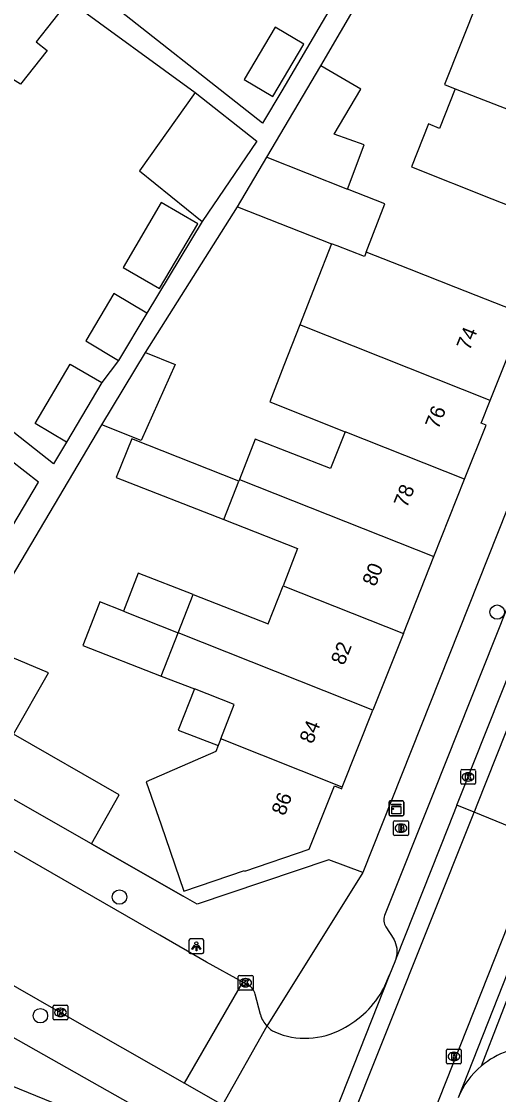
# Model space of a CAD drawing. Extents: x 160026 to 161302, y 384757 to 385701.
# Drawn here: x 160426.3 to 160458.6, y 385061.5 to 385134.3 of the extents above; entities that cross this region are included whole.
import ezdxf

# ---------------------------------------------------------------- set-up
doc = ezdxf.new("R2010")
doc.units = 0
for name, color, linetype in [('IMGEO_Boom', 7, 'Continuous'), ('IMGEO_Brandkraan', 7, 'Continuous'), ('IMGEO_Kast', 7, 'Continuous'), ('IMGEO_Kolk', 7, 'Continuous'), ('IMGEO_Lichtpunt', 7, 'Continuous'), ('IMGEO_Muur', 7, 'Continuous'), ('IMGEO_Pand', 7, 'Continuous'), ('IMGEO_Pand_nummerreeks', 7, 'Continuous'), ('IMGEO_Rijbaan_lokaal_gesloten', 7, 'Continuous'), ('IMGEO_Rijbaan_lokaal_open', 7, 'Continuous'), ('IMGEO_Rioolput', 7, 'Continuous'), ('IMGEO_Voetpad_open', 7, 'Continuous')]:
    doc.layers.add(name, color=color, linetype=linetype)

msp = doc.modelspace()

# ---------------------------------------------------------------- linework, layer by layer
at = {"layer": 'IMGEO_Boom'}
for centre in [(160458.507, 385094.238), (160432.899, 385074.913), (160427.536, 385066.863)]:
    msp.add_circle(centre, 0.489, dxfattribs=at)
at = {"layer": 'IMGEO_Brandkraan'}
for p, q in [((160451.56, 385080.088), (160452.412, 385080.088)), ((160451.485, 385079.162), (160451.485, 385080.014)), ((160451.973, 385079.868), (160451.998, 385079.868)), ((160452.486, 385080.014), (160452.486, 385079.162)), ((160452.412, 385079.088), (160451.56, 385079.088)), ((160451.996, 385079.308), (160451.971, 385079.308))]:
    msp.add_line(p, q, dxfattribs=at)
for points in [[(160451.56, 385080.088), (160452.412, 385080.088)], [(160451.485, 385079.162), (160451.485, 385080.014)], [(160451.833, 385079.788), (160451.833, 385079.388), (160452.046, 385079.388)], [(160452.064, 385079.788), (160451.833, 385079.788)], [(160452.012, 385079.707), (160451.958, 385079.707), (160451.958, 385079.631)], [(160451.958, 385079.631), (160452.011, 385079.631)], [(160452.02, 385079.555), (160451.958, 385079.555), (160451.958, 385079.474)], [(160451.958, 385079.474), (160452.02, 385079.474)], [(160452.486, 385080.014), (160452.486, 385079.162)], [(160452.412, 385079.088), (160451.56, 385079.088)]]:
    msp.add_lwpolyline(points, dxfattribs=at)
for centre, radius, start, end in [((160451.562, 385080.012), 0.0765, 91.55205, 178.44795), ((160451.562, 385080.012), 0.0765, 91.55205, 178.44795), ((160452.41, 385080.012), 0.0765, 1.55205, 88.44795), ((160452.41, 385080.012), 0.0765, 1.55205, 88.44795), ((160452.013, 385079.669), 0.0379, 267.82845, 90.93552), ((160452.021, 385079.514), 0.0404, 269.87594, 90.50774), ((160452.052, 385079.639), 0.251, 268.66757, 293.53466), ((160452.068, 385079.643), 0.145, 59.4692, 91.53667), ((160452.093, 385079.69), 0.0922, 285.51372, 58.15012), ((160452.098, 385079.498), 0.105, 301.31148, 78.98903), ((160451.562, 385079.164), 0.0765, 181.55205, 268.44795), ((160451.562, 385079.164), 0.0765, 181.55205, 268.44795), ((160452.41, 385079.164), 0.0765, 271.55205, 358.44795), ((160452.41, 385079.164), 0.0765, 271.55205, 358.44795)]:
    msp.add_arc(centre, radius, start, end, dxfattribs=at)
for centre, major_axis, ratio, start_param, end_param in [((160451.972, 385079.588), (-0.387, 0.002), 0.722429, 4.712389, 7.853982), ((160451.997, 385079.588), (-0.39, 0.002), 0.717154, 1.570796, 4.712389)]:
    msp.add_ellipse(centre, major_axis=major_axis, ratio=ratio, start_param=start_param, end_param=end_param, dxfattribs=at)
at = {"layer": 'IMGEO_Kast'}
for p, q in [((160451.176, 385080.508), (160451.176, 385081.349)), ((160451.176, 385081.349), (160451.176, 385080.508)), ((160451.251, 385081.433), (160452.092, 385081.433)), ((160452.092, 385081.433), (160451.251, 385081.433)), ((160452.176, 385081.358), (160452.176, 385080.517)), ((160452.176, 385080.517), (160452.176, 385081.358)), ((160452.101, 385080.433), (160451.26, 385080.433)), ((160451.26, 385080.433), (160452.101, 385080.433))]:
    msp.add_line(p, q, dxfattribs=at)
for points in [[(160451.371, 385081.223), (160451.971, 385081.223), (160451.971, 385081.138), (160451.371, 385081.138), (160451.371, 385081.223)], [(160451.371, 385081.048), (160451.971, 385081.048), (160451.971, 385080.559), (160451.371, 385080.559), (160451.371, 385081.048)]]:
    msp.add_lwpolyline(points, dxfattribs=at)
msp.add_circle((160451.455, 385080.897), 0.0377, dxfattribs=at)
for centre, start, end in [((160451.254, 385081.355), 92.4484, 184.28452), ((160451.254, 385081.355), 92.4484, 184.28452), ((160452.098, 385081.355), 2.4484, 94.28452), ((160452.098, 385081.355), 2.4484, 94.28452), ((160451.254, 385080.511), 182.4484, 274.28452), ((160451.254, 385080.511), 182.4484, 274.28452), ((160452.098, 385080.511), 272.4484, 4.28452), ((160452.098, 385080.511), 272.4484, 4.28452)]:
    msp.add_arc(centre, 0.0779, start, end, dxfattribs=at)
at = {"layer": 'IMGEO_Kolk'}
for p, q in [((160456.034, 385082.633), (160456.034, 385083.485)), ((160456.109, 385083.559), (160456.961, 385083.559)), ((160456.522, 385083.339), (160456.547, 385083.339)), ((160457.035, 385083.485), (160457.035, 385082.633)), ((160456.961, 385082.559), (160456.109, 385082.559)), ((160456.545, 385082.779), (160456.52, 385082.779)), ((160440.953, 385068.676), (160440.953, 385069.528)), ((160441.028, 385069.602), (160441.88, 385069.602)), ((160441.441, 385069.382), (160441.466, 385069.382)), ((160441.954, 385069.528), (160441.954, 385068.676)), ((160441.88, 385068.602), (160441.028, 385068.602)), ((160441.464, 385068.822), (160441.439, 385068.822)), ((160428.399, 385066.665), (160428.399, 385067.517)), ((160428.474, 385067.591), (160429.326, 385067.591)), ((160428.887, 385067.371), (160428.912, 385067.371)), ((160429.4, 385067.517), (160429.4, 385066.665)), ((160429.326, 385066.591), (160428.474, 385066.591)), ((160428.91, 385066.811), (160428.885, 385066.811))]:
    msp.add_line(p, q, dxfattribs=at)
for points in [[(160456.034, 385082.633), (160456.034, 385083.485)], [(160456.109, 385083.559), (160456.961, 385083.559)], [(160456.355, 385083.259), (160456.478, 385083.259), (160456.478, 385083.108), (160456.608, 385083.259), (160456.772, 385083.259), (160456.626, 385083.108), (160456.779, 385082.859), (160456.627, 385082.859), (160456.542, 385083.023), (160456.478, 385082.956), (160456.478, 385082.859), (160456.355, 385082.859), (160456.355, 385083.259)], [(160457.035, 385083.485), (160457.035, 385082.633)], [(160456.961, 385082.559), (160456.109, 385082.559)], [(160440.953, 385068.676), (160440.953, 385069.528)], [(160441.028, 385069.602), (160441.88, 385069.602)], [(160441.274, 385069.302), (160441.397, 385069.302), (160441.397, 385069.151), (160441.527, 385069.302), (160441.691, 385069.302), (160441.545, 385069.151), (160441.698, 385068.902), (160441.546, 385068.902), (160441.461, 385069.066), (160441.397, 385068.999), (160441.397, 385068.902), (160441.274, 385068.902), (160441.274, 385069.302)], [(160441.954, 385069.528), (160441.954, 385068.676)], [(160441.88, 385068.602), (160441.028, 385068.602)], [(160428.399, 385066.665), (160428.399, 385067.517)], [(160428.474, 385067.591), (160429.326, 385067.591)], [(160428.72, 385067.291), (160428.843, 385067.291), (160428.843, 385067.14), (160428.973, 385067.291), (160429.137, 385067.291), (160428.991, 385067.14), (160429.144, 385066.891), (160428.992, 385066.891), (160428.907, 385067.055), (160428.843, 385066.988), (160428.843, 385066.891), (160428.72, 385066.891), (160428.72, 385067.291)], [(160429.4, 385067.517), (160429.4, 385066.665)], [(160429.326, 385066.591), (160428.474, 385066.591)]]:
    msp.add_lwpolyline(points, dxfattribs=at)
for centre, start, end in [((160456.111, 385083.483), 91.55205, 178.44795), ((160456.111, 385083.483), 91.55205, 178.44795), ((160456.959, 385083.483), 1.55205, 88.44795), ((160456.959, 385083.483), 1.55205, 88.44795), ((160456.111, 385082.635), 181.55205, 268.44795), ((160456.111, 385082.635), 181.55205, 268.44795), ((160456.959, 385082.635), 271.55205, 358.44795), ((160456.959, 385082.635), 271.55205, 358.44795), ((160441.03, 385069.526), 91.55205, 178.44795), ((160441.03, 385069.526), 91.55205, 178.44795), ((160441.878, 385069.526), 1.55205, 88.44795), ((160441.878, 385069.526), 1.55205, 88.44795), ((160441.03, 385068.678), 181.55205, 268.44795), ((160441.03, 385068.678), 181.55205, 268.44795), ((160441.878, 385068.678), 271.55205, 358.44795), ((160441.878, 385068.678), 271.55205, 358.44795), ((160428.476, 385067.515), 91.55205, 178.44795), ((160428.476, 385067.515), 91.55205, 178.44795), ((160429.324, 385067.515), 1.55205, 88.44795), ((160429.324, 385067.515), 1.55205, 88.44795), ((160428.476, 385066.667), 181.55205, 268.44795), ((160428.476, 385066.667), 181.55205, 268.44795), ((160429.324, 385066.667), 271.55205, 358.44795), ((160429.324, 385066.667), 271.55205, 358.44795)]:
    msp.add_arc(centre, 0.0765, start, end, dxfattribs=at)
for centre, major_axis, ratio, start_param, end_param in [((160456.521, 385083.059), (-0.387, 0.002), 0.722429, 4.712389, 7.853982), ((160456.546, 385083.059), (-0.39, 0.002), 0.717154, 1.570796, 4.712389), ((160441.44, 385069.102), (-0.387, 0.002), 0.722429, 4.712389, 7.853982), ((160441.465, 385069.102), (-0.39, 0.002), 0.717154, 1.570796, 4.712389), ((160428.886, 385067.091), (-0.387, 0.002), 0.722429, 4.712389, 7.853982), ((160428.911, 385067.091), (-0.39, 0.002), 0.717154, 1.570796, 4.712389)]:
    msp.add_ellipse(centre, major_axis=major_axis, ratio=ratio, start_param=start_param, end_param=end_param, dxfattribs=at)
at = {"layer": 'IMGEO_Lichtpunt'}
for p, q in [((160437.613, 385071.976), (160437.613, 385071.169)), ((160437.613, 385071.976), (160437.613, 385071.169)), ((160438.515, 385072.071), (160437.707, 385072.071)), ((160438.515, 385072.071), (160437.707, 385072.071)), ((160438.609, 385071.169), (160438.609, 385071.976)), ((160438.609, 385071.169), (160438.609, 385071.976)), ((160437.707, 385071.075), (160438.515, 385071.075)), ((160437.707, 385071.075), (160438.515, 385071.075))]:
    msp.add_line(p, q, dxfattribs=at)
for points in [[(160437.987, 385071.64), (160438.026, 385071.612), (160437.838, 385071.35), (160437.8, 385071.377), (160437.987, 385071.64)], [(160438.089, 385071.592), (160438.136, 385071.592), (160438.136, 385071.27), (160438.089, 385071.27), (160438.089, 385071.592)], [(160438.199, 385071.612), (160438.237, 385071.639), (160438.424, 385071.377), (160438.385, 385071.349), (160438.199, 385071.612)]]:
    msp.add_lwpolyline(points, dxfattribs=at)
msp.add_circle((160438.112, 385071.774), 0.0994, dxfattribs=at)
for centre, start, end in [((160437.707, 385071.976), 90, 180), ((160437.707, 385071.976), 90, 180), ((160438.515, 385071.976), 0, 90), ((160438.515, 385071.976), 0, 90), ((160437.707, 385071.169), 180, 270), ((160437.707, 385071.169), 180, 270), ((160438.515, 385071.169), 270, 0), ((160438.515, 385071.169), 270, 360)]:
    msp.add_arc(centre, 0.0946, start, end, dxfattribs=at)
at = {"layer": 'IMGEO_Muur'}
msp.add_lwpolyline([(160430.992, 385078.531), (160437.229, 385074.968)], dxfattribs=at)
at = {"layer": 'IMGEO_Pand'}
for points in [[(160429.474, 385135.723), (160427.258, 385132.915), (160427.989, 385132.338), (160426.18, 385130.045), (160425.462, 385130.507)], [(160465.033, 385126.08), (160467.261, 385131.724), (160462.611, 385133.56), (160457.19, 385135.7), (160454.945, 385130.013), (160455.658, 385129.731)], [(160441.357, 385130.364), (160443.306, 385129.209), (160445.408, 385132.754), (160443.459, 385133.91), (160441.357, 385130.364)], [(160442.894, 385125.095), (160446.548, 385131.291)], [(160448.359, 385122.933), (160449.491, 385125.921), (160447.465, 385126.661), (160449.254, 385129.695), (160446.548, 385131.291)], [(160455.658, 385129.731), (160454.597, 385127.046), (160453.842, 385127.344), (160452.692, 385124.43), (160458.155, 385122.273), (160462.805, 385120.437), (160465.033, 385126.08)], [(160455.658, 385129.731), (160465.033, 385126.08)], [(160438.025, 385129.48), (160434.248, 385124.172), (160438.496, 385120.74)], [(160438.025, 385129.48), (160442.211, 385126.171), (160438.496, 385120.74)], [(160440.904, 385121.721), (160442.894, 385125.095)], [(160442.894, 385125.095), (160448.359, 385122.933)], [(160449.623, 385118.659), (160450.901, 385121.927), (160448.359, 385122.933)], [(160435.734, 385122.018), (160433.14, 385117.609), (160435.617, 385116.185), (160438.211, 385120.575), (160435.734, 385122.018)], [(160440.904, 385121.721), (160447.284, 385119.225)], [(160447.284, 385119.225), (160446.219, 385116.502), (160445.128, 385113.713)], [(160449.623, 385118.659), (160449.504, 385118.356), (160447.661, 385119.077), (160447.284, 385119.225)], [(160458.029, 385108.592), (160460.354, 385114.427), (160455.703, 385116.262), (160452.563, 385117.5), (160449.623, 385118.659)], [(160434.745, 385114.524), (160432.524, 385115.84), (160430.619, 385112.626), (160432.84, 385111.309)], [(160434.745, 385114.524), (160432.84, 385111.309)], [(160445.128, 385113.713), (160444.054, 385110.967), (160443.087, 385108.495), (160448.195, 385106.467)], [(160458.029, 385108.592), (160445.128, 385113.713)], [(160431.712, 385106.94), (160434.664, 385111.839)], [(160434.664, 385111.839), (160436.672, 385111.042), (160434.369, 385105.885), (160431.712, 385106.94)], [(160429.309, 385105.761), (160427.177, 385107.022), (160429.566, 385111.062), (160431.699, 385109.8)], [(160431.699, 385109.8), (160429.309, 385105.761)], [(160456.303, 385103.248), (160457.758, 385106.913), (160457.417, 385107.056), (160458.029, 385108.592)], [(160448.195, 385106.467), (160447.218, 385103.97), (160442.104, 385105.97), (160441.036, 385103.239)], [(160456.303, 385103.248), (160448.195, 385106.467)], [(160440.988, 385103.117), (160433.731, 385105.998), (160432.683, 385103.358), (160439.969, 385100.509)], [(160439.969, 385100.509), (160440.988, 385103.117)], [(160441.036, 385103.239), (160440.988, 385103.117)], [(160441.036, 385103.239), (160454.22, 385098.005)], [(160454.22, 385098.005), (160456.303, 385103.248)], [(160439.969, 385100.509), (160444.976, 385098.551), (160443.99, 385096.031)], [(160452.15, 385092.792), (160454.22, 385098.005)], [(160437.892, 385095.427), (160434.17, 385096.882), (160433.162, 385094.305)], [(160436.877, 385092.83), (160437.892, 385095.427)], [(160437.892, 385095.427), (160442.976, 385093.439), (160443.99, 385096.031)], [(160443.99, 385096.031), (160452.15, 385092.792)], [(160433.162, 385094.305), (160431.565, 385094.939), (160431.492, 385094.753), (160431.293, 385094.245), (160430.41, 385091.985), (160435.733, 385089.904)], [(160433.162, 385094.305), (160436.877, 385092.83)], [(160435.733, 385089.904), (160436.877, 385092.83)], [(160450.083, 385087.587), (160436.877, 385092.83)], [(160452.15, 385092.792), (160450.083, 385087.587)], [(160430.992, 385078.531), (160432.889, 385081.856), (160425.703, 385085.956), (160428.077, 385090.118), (160424.153, 385091.772)], [(160435.733, 385089.904), (160437.979, 385089.026)], [(160437.979, 385089.026), (160436.889, 385086.238), (160439.587, 385085.183)], [(160439.765, 385085.638), (160440.677, 385087.971), (160437.979, 385089.026)], [(160448.009, 385082.365), (160450.083, 385087.587)], [(160439.587, 385085.183), (160439.433, 385084.79), (160434.711, 385082.723), (160435.731, 385079.821), (160437.258, 385075.314), (160441.379, 385076.721), (160441.399, 385076.66), (160445.764, 385078.151), (160447.468, 385082.458), (160447.967, 385082.258), (160448.009, 385082.365)], [(160439.765, 385085.638), (160439.587, 385085.183)], [(160448.009, 385082.365), (160439.765, 385085.638)], [(160430.992, 385078.531), (160420.134, 385084.726)], [(160416.228, 385058.883), (160418.844, 385057.768), (160418.33, 385056.562), (160421.77, 385055.094), (160424.883, 385062.397), (160437.345, 385057.328), (160437.192, 385056.925), (160437.809, 385056.671), (160436.374, 385053.189), (160435.815, 385053.42), (160433.49, 385047.781)]]:
    msp.add_lwpolyline(points, dxfattribs=at)
at = {"layer": 'IMGEO_Rijbaan_lokaal_gesloten'}
for points in [[(160441.257, 385069.142), (160438.8, 385070.504), (160435.644, 385072.318), (160423.083, 385079.537)], [(160408.745, 385078.592), (160410.666, 385077.515), (160413.918, 385075.639), (160418.139, 385073.218), (160424.416, 385069.645), (160428.901, 385067.092), (160437.316, 385062.291)], [(160437.316, 385062.291), (160441.257, 385069.142)]]:
    msp.add_lwpolyline(points, dxfattribs=at)
at = {"layer": 'IMGEO_Rijbaan_lokaal_open'}
for points in [[(160455.778, 385081.134), (160455.964, 385081.607), (160471.018, 385119.416), (160484.621, 385153.583)], [(160485.703, 385153.152), (160472.155, 385118.996), (160457.14, 385081.141), (160456.95, 385080.661)], [(160455.778, 385081.134), (160455.177, 385079.664), (160451.665, 385070.767)], [(160456.95, 385080.661), (160455.778, 385081.134)], [(160444.248, 385048.841), (160445.179, 385051.173), (160456.884, 385080.495), (160456.95, 385080.661)], [(160461.545, 385078.805), (160456.95, 385080.661)], [(160461.545, 385078.805), (160461.163, 385077.845), (160449.849, 385049.309), (160448.949, 385047.038)], [(160462.221, 385077.395), (160455.854, 385061.298)], [(160457.441, 385063.46), (160459.941, 385069.896), (160462.004, 385075.033)], [(160451.665, 385070.767), (160451.564, 385070.512), (160451.217, 385069.636)], [(160451.217, 385069.636), (160444.275, 385052.096)], [(160450.82, 385068.727), (160451.217, 385069.636)], [(160441.637, 385068.931), (160441.441, 385069.04), (160441.257, 385069.142)], [(160442.461, 385066.94), (160442.105, 385068.325)], [(160442.902, 385066.151), (160439.877, 385060.829)], [(160437.316, 385062.291), (160439.877, 385060.829)]]:
    msp.add_lwpolyline(points, dxfattribs=at)
for centre, radius, start, end in [((160441.142, 385068.065), 0.997, 15.10373, 60.25245), ((160445.025, 385071.836), 6.576, 297.01428, 331.78995), ((160444.231, 385067.412), 1.832, 194.91909, 223.48565), ((160444.248, 385067.427), 1.854, 223.47168, 243.87053), ((160445.501, 385070.576), 5.24, 246.73836, 298.63582), ((160461.012, 385059.187), 5.568, 108.84467, 129.88312), ((160461.036, 385059.158), 5.607, 129.88196, 157.55753)]:
    msp.add_arc(centre, radius, start, end, dxfattribs=at)
at = {"layer": 'IMGEO_Rioolput'}
for p, q in [((160455.077, 385063.678), (160455.077, 385064.53)), ((160455.152, 385064.604), (160456.004, 385064.604)), ((160455.565, 385064.384), (160455.59, 385064.384)), ((160456.078, 385064.53), (160456.078, 385063.678)), ((160456.004, 385063.604), (160455.152, 385063.604)), ((160455.588, 385063.824), (160455.563, 385063.824))]:
    msp.add_line(p, q, dxfattribs=at)
for points in [[(160455.077, 385063.678), (160455.077, 385064.53)], [(160455.152, 385064.604), (160456.004, 385064.604)], [(160455.666, 385064.302), (160455.414, 385064.304), (160455.414, 385063.904)], [(160455.414, 385063.904), (160455.538, 385063.904), (160455.538, 385064.066), (160455.549, 385064.066)], [(160455.592, 385064.223), (160455.538, 385064.223), (160455.538, 385064.142)], [(160455.538, 385064.142), (160455.59, 385064.142)], [(160456.078, 385064.53), (160456.078, 385063.678)], [(160456.004, 385063.604), (160455.152, 385063.604)], [(160455.596, 385064.037), (160455.667, 385063.904), (160455.807, 385063.904), (160455.742, 385064.03)]]:
    msp.add_lwpolyline(points, dxfattribs=at)
for centre, radius, start, end in [((160455.154, 385064.528), 0.0765, 91.55205, 178.44795), ((160455.154, 385064.528), 0.0765, 91.55205, 178.44795), ((160455.548, 385064.013), 0.0533, 26.02933, 88.69889), ((160455.574, 385064.331), 0.19, 274.7715, 282.96867), ((160455.598, 385064.127), 0.0964, 77.00612, 93.18647), ((160455.612, 385064.184), 0.0378, 276.66336, 79.67722), ((160455.665, 385064.192), 0.109, 350.36119, 89.41601), ((160455.663, 385064.192), 0.112, 277.58423, 350.98172), ((160455.647, 385063.977), 0.108, 29.51342, 73.79051), ((160456.002, 385064.528), 0.0765, 1.55205, 88.44795), ((160456.002, 385064.528), 0.0765, 1.55205, 88.44795), ((160455.154, 385063.68), 0.0765, 181.55205, 268.44795), ((160455.154, 385063.68), 0.0765, 181.55205, 268.44795), ((160456.002, 385063.68), 0.0765, 271.55205, 358.44795), ((160456.002, 385063.68), 0.0765, 271.55205, 358.44795)]:
    msp.add_arc(centre, radius, start, end, dxfattribs=at)
for centre, major_axis, ratio, start_param, end_param in [((160455.564, 385064.104), (-0.387, 0.002), 0.722429, 4.712389, 7.853982), ((160455.589, 385064.104), (-0.39, 0.002), 0.717154, 1.570796, 4.712389)]:
    msp.add_ellipse(centre, major_axis=major_axis, ratio=ratio, start_param=start_param, end_param=end_param, dxfattribs=at)
at = {"layer": 'IMGEO_Voetpad_open'}
for points in [[(160482.071, 385152.056), (160474.809, 385133.801), (160473.345, 385130.12), (160469.335, 385120.04), (160468.756, 385118.584), (160465.855, 385111.292), (160454.199, 385081.989), (160450.873, 385073.66)], [(160450.45, 385140.726), (160445.811, 385132.814), (160443.905, 385129.599), (160442.603, 385127.403), (160431.226, 385136.373)], [(160446.548, 385131.291), (160451.894, 385140.439)], [(160471.611, 385136.751), (160472.517, 385134.799), (160467.001, 385120.904), (160449.407, 385076.581)], [(160429.474, 385135.723), (160438.025, 385129.48)], [(160434.664, 385111.839), (160440.904, 385121.721)], [(160438.496, 385120.74), (160434.745, 385114.524)], [(160429.309, 385105.761), (160428.436, 385104.286), (160414.516, 385115.27)], [(160432.84, 385111.309), (160431.699, 385109.8)], [(160424.153, 385091.772), (160423.001, 385092.257), (160431.712, 385106.94)], [(160417.444, 385086.258), (160427.408, 385103.06), (160424.617, 385105.23)], [(160449.407, 385076.581), (160447.104, 385077.448), (160438.166, 385074.433), (160437.229, 385074.968), (160430.992, 385078.531)], [(160449.407, 385076.581), (160442.902, 385066.151)], [(160450.971, 385072.903), (160451.505, 385072.053)], [(160424.98, 385065.798), (160438.609, 385058.093)]]:
    msp.add_lwpolyline(points, dxfattribs=at)
for centre, radius, start, end in [((160451.682, 385073.38), 0.856, 160.91303, 213.83976), ((160450.122, 385071.228), 1.611, 343.37341, 30.81081)]:
    msp.add_arc(centre, radius, start, end, dxfattribs=at)

# ---------------------------------------------------------------- texts
at = {"layer": 'IMGEO_Pand_nummerreeks'}
for s, rotation, p in [('74', 68.23927, (160456.642, 385111.926)), ('76', 68.23927, (160454.512, 385106.591)), ('78', 68.23841, (160452.383, 385101.258)), ('80', 68.23927, (160450.253, 385095.923)), ('82', 68.23841, (160448.121, 385090.581)), ('84', 68.23927, (160445.993, 385085.25)), ('86', 69.15028, (160444.102, 385080.377))]:
    msp.add_text(s, height=1, rotation=rotation, dxfattribs=at).set_placement(p)

doc.saveas('drawing.dxf')
